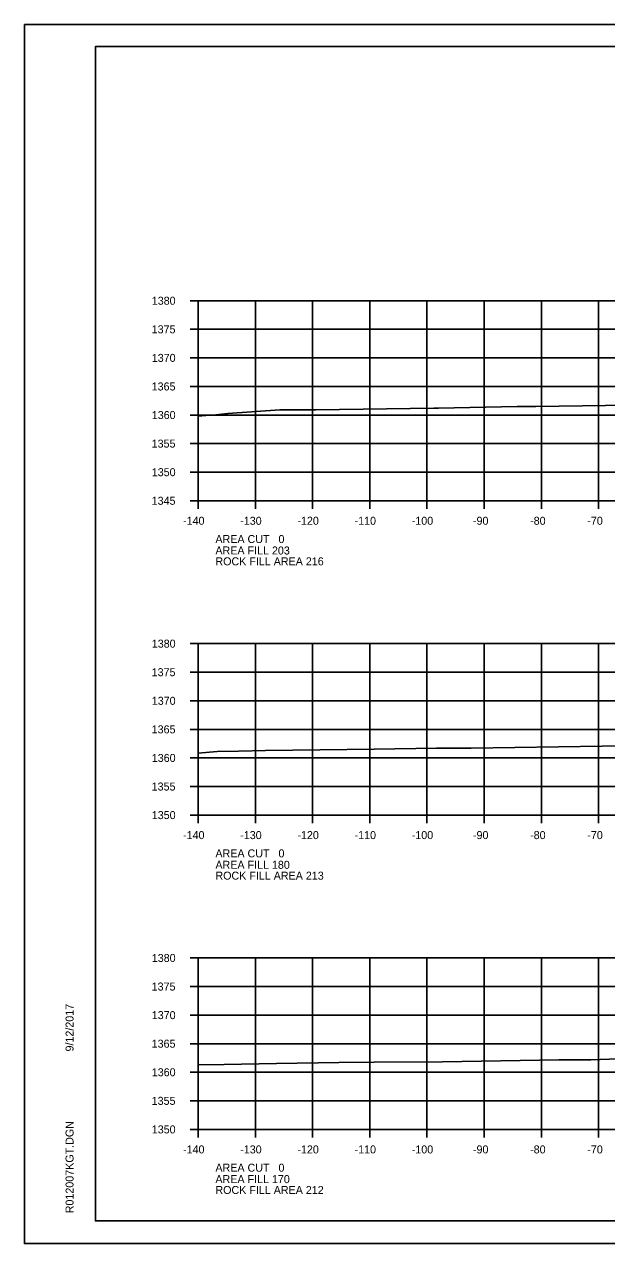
# Model space of a CAD drawing. Extents: x 1374311 to 1383814, y 384102 to 406278.
# Drawn here: x 1381458.2 to 1381560.1, y 389871.4 to 390084.7 of the extents above; entities that cross this region are included whole.
import ezdxf

# ---------------------------------------------------------------- set-up
doc = ezdxf.new("R2010")
doc.units = 0
for name, color, linetype in [('R_Axis', 7, 'Continuous'), ('R_Axis Annot', 7, 'Continuous'), ('R_Border', 7, 'Continuous'), ('R_Exist Surface', 7, 'Continuous'), ('R_Grid', 7, 'Continuous'), ('R_No Plot', 7, 'Continuous')]:
    doc.layers.add(name, color=color, linetype=linetype)

msp = doc.modelspace()

# ---------------------------------------------------------------- linework, layer by layer
at = {"layer": 'R_Axis'}
for p, q in [((1381487.26, 390036.37), (1381488.66, 390036.37)), ((1381488.66, 390001.37), (1381488.66, 390036.37)), ((1381487.26, 390031.37), (1381488.66, 390031.37)), ((1381487.26, 390026.37), (1381488.66, 390026.37)), ((1381487.26, 390021.37), (1381488.66, 390021.37)), ((1381487.26, 390016.37), (1381488.66, 390016.37)), ((1381487.26, 390011.37), (1381488.66, 390011.37)), ((1381487.26, 390006.37), (1381488.66, 390006.37)), ((1381487.26, 390001.37), (1381488.66, 390001.37)), ((1381488.66, 390001.37), (1381768.66, 390001.37)), ((1381488.66, 389999.97), (1381488.66, 390001.37)), ((1381498.66, 389999.97), (1381498.66, 390001.37)), ((1381508.66, 389999.97), (1381508.66, 390001.37)), ((1381518.66, 389999.97), (1381518.66, 390001.37)), ((1381528.66, 389999.97), (1381528.66, 390001.37)), ((1381538.66, 389999.97), (1381538.66, 390001.37)), ((1381548.66, 389999.97), (1381548.66, 390001.37)), ((1381558.66, 389999.97), (1381558.66, 390001.37)), ((1381487.26, 389976.37), (1381488.66, 389976.37)), ((1381488.66, 389946.37), (1381488.66, 389976.37)), ((1381487.26, 389971.37), (1381488.66, 389971.37)), ((1381487.26, 389966.37), (1381488.66, 389966.37)), ((1381487.26, 389961.37), (1381488.66, 389961.37)), ((1381487.26, 389956.37), (1381488.66, 389956.37)), ((1381487.26, 389951.37), (1381488.66, 389951.37)), ((1381487.26, 389946.37), (1381488.66, 389946.37)), ((1381488.66, 389946.37), (1381768.66, 389946.37)), ((1381488.66, 389944.97), (1381488.66, 389946.37)), ((1381498.66, 389944.97), (1381498.66, 389946.37)), ((1381508.66, 389944.97), (1381508.66, 389946.37)), ((1381518.66, 389944.97), (1381518.66, 389946.37)), ((1381528.66, 389944.97), (1381528.66, 389946.37)), ((1381538.66, 389944.97), (1381538.66, 389946.37)), ((1381548.66, 389944.97), (1381548.66, 389946.37)), ((1381558.66, 389944.97), (1381558.66, 389946.37)), ((1381487.26, 389921.37), (1381488.66, 389921.37)), ((1381488.66, 389891.37), (1381488.66, 389921.37)), ((1381487.26, 389916.37), (1381488.66, 389916.37)), ((1381487.26, 389911.37), (1381488.66, 389911.37)), ((1381487.26, 389906.37), (1381488.66, 389906.37)), ((1381487.26, 389901.37), (1381488.66, 389901.37)), ((1381487.26, 389896.37), (1381488.66, 389896.37)), ((1381487.26, 389891.37), (1381488.66, 389891.37)), ((1381488.66, 389891.37), (1381768.66, 389891.37)), ((1381488.66, 389889.97), (1381488.66, 389891.37)), ((1381498.66, 389889.97), (1381498.66, 389891.37)), ((1381508.66, 389889.97), (1381508.66, 389891.37)), ((1381518.66, 389889.97), (1381518.66, 389891.37)), ((1381528.66, 389889.97), (1381528.66, 389891.37)), ((1381538.66, 389889.97), (1381538.66, 389891.37)), ((1381548.66, 389889.97), (1381548.66, 389891.37)), ((1381558.66, 389889.97), (1381558.66, 389891.37))]:
    msp.add_line(p, q, dxfattribs=at)
at = {"layer": 'R_Border'}
for p, q in [((1381470.66, 390080.83), (1381786.84, 390080.83)), ((1381470.66, 389875.37), (1381470.66, 390080.83)), ((1381470.66, 389875.37), (1381470.66, 389875.37)), ((1381786.84, 389875.37), (1381470.66, 389875.37))]:
    msp.add_line(p, q, dxfattribs=at)
at = {"layer": 'R_Exist Surface'}
for points in [[(1381488.66, 390016.2), (1381490, 390016.3), (1381491.76, 390016.42), (1381493.85, 390016.61), (1381502.9, 390017.27), (1381509.25, 390017.29), (1381529.84, 390017.57), (1381530.24, 390017.58), (1381530.36, 390017.58), (1381530.67, 390017.59), (1381544.44, 390017.88), (1381547.69, 390017.88), (1381568.02, 390018.18)], [(1381488.66, 389957.18), (1381491.99, 389957.52), (1381495.7, 389957.55), (1381500.39, 389957.65), (1381519.45, 389957.89), (1381530.32, 389958.06), (1381536.41, 389958.09), (1381559.3, 389958.43), (1381563.35, 389958.49), (1381563.98, 389958.5), (1381569.16, 389958.57), (1381591.08, 389958.89), (1381601.24, 389959.03), (1381607.17, 389959.12), (1381623.18, 389958.98), (1381625.05, 389958.99), (1381629.45, 389958.99), (1381647.23, 389959.45), (1381655.32, 389959.81), (1381666.78, 389959.96), (1381668, 389959.97), (1381669.71, 389960.02), (1381685.16, 389960.38)], [(1381488.66, 389902.68), (1381493.2, 389902.73), (1381502.37, 389902.92), (1381513.22, 389903.06), (1381519.41, 389903.15), (1381531.4, 389903.22), (1381551.71, 389903.52), (1381557.32, 389903.57), (1381560.58, 389903.65), (1381574.95, 389903.88), (1381577.08, 389903.91), (1381595.09, 389904.17), (1381605.59, 389904.33), (1381615.8, 389904.23), (1381622.61, 389904.3), (1381638.57, 389904.27), (1381641.93, 389904.36), (1381650.07, 389904.72), (1381656.77, 389904.98), (1381658.31, 389905.05), (1381666.99, 389905.15), (1381679.33, 389905.49), (1381681.22, 389905.52)]]:
    msp.add_lwpolyline(points, dxfattribs=at)
at = {"layer": 'R_Grid'}
for p, q in [((1381488.66, 390036.37), (1381768.66, 390036.37)), ((1381488.66, 390001.37), (1381488.66, 390036.37)), ((1381498.66, 390001.37), (1381498.66, 390036.37)), ((1381508.66, 390001.37), (1381508.66, 390036.37)), ((1381518.66, 390001.37), (1381518.66, 390036.37)), ((1381528.66, 390001.37), (1381528.66, 390036.37)), ((1381538.66, 390001.37), (1381538.66, 390036.37)), ((1381548.66, 390001.37), (1381548.66, 390036.37)), ((1381558.66, 390001.37), (1381558.66, 390036.37)), ((1381488.66, 390031.37), (1381768.66, 390031.37)), ((1381488.66, 390026.37), (1381768.66, 390026.37)), ((1381488.66, 390021.37), (1381768.66, 390021.37)), ((1381488.66, 390016.37), (1381768.66, 390016.37)), ((1381488.66, 390011.37), (1381768.66, 390011.37)), ((1381488.66, 390006.37), (1381768.66, 390006.37)), ((1381488.66, 390001.37), (1381768.66, 390001.37)), ((1381488.66, 389976.37), (1381768.66, 389976.37)), ((1381488.66, 389946.37), (1381488.66, 389976.37)), ((1381498.66, 389946.37), (1381498.66, 389976.37)), ((1381508.66, 389946.37), (1381508.66, 389976.37)), ((1381518.66, 389946.37), (1381518.66, 389976.37)), ((1381528.66, 389946.37), (1381528.66, 389976.37)), ((1381538.66, 389946.37), (1381538.66, 389976.37)), ((1381548.66, 389946.37), (1381548.66, 389976.37)), ((1381558.66, 389946.37), (1381558.66, 389976.37)), ((1381488.66, 389971.37), (1381768.66, 389971.37)), ((1381488.66, 389966.37), (1381768.66, 389966.37)), ((1381488.66, 389961.37), (1381768.66, 389961.37)), ((1381488.66, 389956.37), (1381768.66, 389956.37)), ((1381488.66, 389951.37), (1381768.66, 389951.37)), ((1381488.66, 389946.37), (1381768.66, 389946.37)), ((1381488.66, 389921.37), (1381768.66, 389921.37)), ((1381488.66, 389891.37), (1381488.66, 389921.37)), ((1381498.66, 389891.37), (1381498.66, 389921.37)), ((1381508.66, 389891.37), (1381508.66, 389921.37)), ((1381518.66, 389891.37), (1381518.66, 389921.37)), ((1381528.66, 389891.37), (1381528.66, 389921.37)), ((1381538.66, 389891.37), (1381538.66, 389921.37)), ((1381548.66, 389891.37), (1381548.66, 389921.37)), ((1381558.66, 389891.37), (1381558.66, 389921.37)), ((1381488.66, 389916.37), (1381768.66, 389916.37)), ((1381488.66, 389911.37), (1381768.66, 389911.37)), ((1381488.66, 389906.37), (1381768.66, 389906.37)), ((1381488.66, 389901.37), (1381768.66, 389901.37)), ((1381488.66, 389896.37), (1381768.66, 389896.37)), ((1381488.66, 389891.37), (1381768.66, 389891.37))]:
    msp.add_line(p, q, dxfattribs=at)
at = {"layer": 'R_No Plot'}
for p, q in [((1381458.26, 390084.73), (1381791.59, 390084.73)), ((1381458.26, 389871.39), (1381791.59, 389871.39))]:
    msp.add_line(p, q, dxfattribs=at)
for points in [[(1381458.25, 390084.73), (1381791.59, 390084.73), (1381791.59, 389871.39), (1381458.25, 389871.39)], [(1381704.58, 390080.83), (1381704.58, 390070.95), (1381740.31, 390070.95), (1381740.31, 390068.03), (1381763.51, 390068.03), (1381763.51, 390044.82), (1381786.84, 390044.82), (1381786.84, 389875.37), (1381470.66, 389875.37), (1381470.66, 390080.83)]]:
    msp.add_lwpolyline(points, close=True, dxfattribs=at)

# ---------------------------------------------------------------- texts
at = {"layer": 'R_Axis Annot'}
for s, p in [('1380', (1381480.53, 390035.67)), ('1375', (1381480.51, 390030.67)), ('1370', (1381480.53, 390025.67)), ('1365', (1381480.51, 390020.67)), ('1360', (1381480.53, 390015.67)), ('1355', (1381480.51, 390010.67)), ('1350', (1381480.53, 390005.67)), ('1345', (1381480.51, 390000.67)), ('-140', (1381486, 389997.17)), ('-130', (1381496, 389997.17)), ('-120', (1381506, 389997.17)), ('-110', (1381516, 389997.17)), ('-100', (1381526, 389997.17)), ('-90', (1381536.7, 389997.17)), ('-80', (1381546.7, 389997.17)), ('-70', (1381556.7, 389997.17)), ('AREA CUT   0', (1381491.66, 389993.97)), ('AREA FILL 203', (1381491.66, 389991.97)), ('ROCK FILL AREA 216', (1381491.66, 389990.07)), ('1380', (1381480.53, 389975.67)), ('1375', (1381480.51, 389970.67)), ('1370', (1381480.53, 389965.67)), ('1365', (1381480.51, 389960.67)), ('1360', (1381480.53, 389955.67)), ('1355', (1381480.51, 389950.67)), ('1350', (1381480.53, 389945.67)), ('-140', (1381486, 389942.17)), ('-130', (1381496, 389942.17)), ('-120', (1381506, 389942.17)), ('-110', (1381516, 389942.17)), ('-100', (1381526, 389942.17)), ('-90', (1381536.7, 389942.17)), ('-80', (1381546.7, 389942.17)), ('-70', (1381556.7, 389942.17)), ('AREA CUT   0', (1381491.66, 389938.97)), ('AREA FILL 180', (1381491.66, 389936.97)), ('ROCK FILL AREA 213', (1381491.66, 389935.07)), ('1380', (1381480.53, 389920.67)), ('1375', (1381480.51, 389915.67)), ('1370', (1381480.53, 389910.67)), ('1365', (1381480.51, 389905.67)), ('1360', (1381480.53, 389900.67)), ('1355', (1381480.51, 389895.67)), ('1350', (1381480.53, 389890.67)), ('-140', (1381486, 389887.17)), ('-130', (1381496, 389887.17)), ('-120', (1381506, 389887.17)), ('-110', (1381516, 389887.17)), ('-100', (1381526, 389887.17)), ('-90', (1381536.7, 389887.17)), ('-80', (1381546.7, 389887.17)), ('-70', (1381556.7, 389887.17)), ('AREA CUT   0', (1381491.66, 389883.97)), ('AREA FILL 170', (1381491.66, 389881.97)), ('ROCK FILL AREA 212', (1381491.66, 389880.07))]:
    msp.add_text(s, height=1.4, dxfattribs=at).set_placement(p)
at = {"layer": 'R_Border'}
for s, p in [('9/12/2017', (1381466.85, 389905.01)), ('R012007KGT.DGN', (1381466.85, 389876.7))]:
    msp.add_text(s, height=1.4, rotation=90, dxfattribs=at).set_placement(p)

doc.saveas('drawing.dxf')
